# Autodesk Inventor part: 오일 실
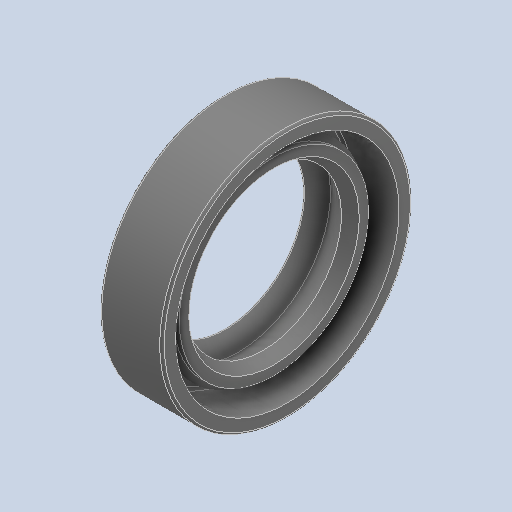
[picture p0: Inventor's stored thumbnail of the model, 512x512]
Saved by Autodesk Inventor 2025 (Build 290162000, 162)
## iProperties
Created: 2025-08
Part Number: 오일 실
Material: 고무
Description: 오일-실
Document SubType Name: Modeling
Designer: infra04
Density: 0.93 g/cm^3
Appearance: 기본값
Author: jhkim
Sending System: Autodesk Inventor 2026
Preprocessor: ST-DEVELOPER v20.1
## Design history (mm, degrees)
feature "Solid1"
node "솔리드1"
